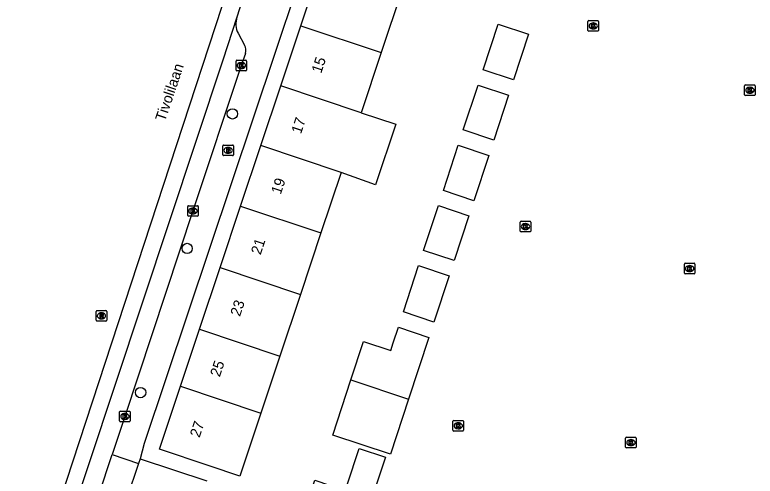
# Model space of a CAD drawing. Extents: x 163150 to 163546, y 380933 to 381635.
# Drawn here: x 163218.8 to 163289.1, y 381514.3 to 381558 of the extents above; entities that cross this region are included whole.
import ezdxf

# ---------------------------------------------------------------- set-up
doc = ezdxf.new("R2010")
doc.units = 0
for name, color, linetype in [('IMGEO_Boom', 7, 'Continuous'), ('IMGEO_Brandkraan', 7, 'Continuous'), ('IMGEO_Fietspad_gesloten', 7, 'Continuous'), ('IMGEO_Kolk', 7, 'Continuous'), ('IMGEO_Openbare_ruimte_label', 7, 'Continuous'), ('IMGEO_Pand', 7, 'Continuous'), ('IMGEO_Pand_nummerreeks', 7, 'Continuous'), ('IMGEO_Rijbaan_lokaal_gesloten', 7, 'Continuous'), ('IMGEO_Rioolput', 7, 'Continuous'), ('IMGEO_Voetpad_open', 7, 'Continuous')]:
    doc.layers.add(name, color=color, linetype=linetype)

msp = doc.modelspace()

# ---------------------------------------------------------------- linework, layer by layer
at = {"layer": 'IMGEO_Boom'}
for centre in [(163239.462, 381548.623), (163235.165, 381535.854), (163230.745, 381522.183)]:
    msp.add_circle(centre, 0.489, dxfattribs=at)
at = {"layer": 'IMGEO_Brandkraan'}
for p, q in [((163238.556, 381544.736), (163238.556, 381545.588)), ((163238.631, 381545.662), (163239.483, 381545.662)), ((163239.044, 381545.442), (163239.069, 381545.442)), ((163239.557, 381545.588), (163239.557, 381544.736)), ((163239.483, 381544.662), (163238.631, 381544.662)), ((163239.067, 381544.882), (163239.042, 381544.882))]:
    msp.add_line(p, q, dxfattribs=at)
for points in [[(163238.556, 381544.736), (163238.556, 381545.588)], [(163238.631, 381545.662), (163239.483, 381545.662)], [(163238.904, 381545.362), (163238.904, 381544.962), (163239.117, 381544.962)], [(163239.135, 381545.362), (163238.904, 381545.362)], [(163239.083, 381545.281), (163239.029, 381545.281), (163239.029, 381545.205)], [(163239.029, 381545.205), (163239.082, 381545.205)], [(163239.091, 381545.129), (163239.029, 381545.129), (163239.029, 381545.048)], [(163239.557, 381545.588), (163239.557, 381544.736)], [(163239.483, 381544.662), (163238.631, 381544.662)], [(163239.029, 381545.048), (163239.091, 381545.048)]]:
    msp.add_lwpolyline(points, dxfattribs=at)
for centre, radius, start, end in [((163238.633, 381545.586), 0.0765, 91.55205, 178.44795), ((163238.633, 381545.586), 0.0765, 91.55205, 178.44795), ((163239.084, 381545.243), 0.0379, 267.82845, 90.93552), ((163239.092, 381545.088), 0.0404, 269.87594, 90.50774), ((163239.139, 381545.217), 0.145, 59.4692, 91.53667), ((163239.164, 381545.264), 0.0922, 285.51372, 58.15012), ((163239.169, 381545.072), 0.105, 301.31148, 78.98903), ((163239.481, 381545.586), 0.0765, 1.55205, 88.44795), ((163239.481, 381545.586), 0.0765, 1.55205, 88.44795), ((163238.633, 381544.738), 0.0765, 181.55205, 268.44795), ((163238.633, 381544.738), 0.0765, 181.55205, 268.44795), ((163239.123, 381545.213), 0.251, 268.66757, 293.53466), ((163239.481, 381544.738), 0.0765, 271.55205, 358.44795), ((163239.481, 381544.738), 0.0765, 271.55205, 358.44795)]:
    msp.add_arc(centre, radius, start, end, dxfattribs=at)
for centre, major_axis, ratio, start_param, end_param in [((163239.043, 381545.162), (-0.387, 0.002), 0.722429, 4.712389, 7.853982), ((163239.068, 381545.162), (-0.39, 0.002), 0.717154, 1.570796, 4.712389)]:
    msp.add_ellipse(centre, major_axis=major_axis, ratio=ratio, start_param=start_param, end_param=end_param, dxfattribs=at)
at = {"layer": 'IMGEO_Fietspad_gesloten'}
for points in [[(163241.214, 381561.974), (163239.892, 381557.795)], [(163239.892, 381557.795), (163238.567, 381553.72), (163220.71, 381500), (163220.06, 381498.046)]]:
    msp.add_lwpolyline(points, dxfattribs=at)
at = {"layer": 'IMGEO_Kolk'}
for p, q in [((163273.225, 381556.542), (163273.225, 381557.394)), ((163273.3, 381557.468), (163274.152, 381557.468)), ((163273.713, 381557.248), (163273.738, 381557.248)), ((163274.226, 381557.394), (163274.226, 381556.542)), ((163274.152, 381556.468), (163273.3, 381556.468)), ((163273.736, 381556.688), (163273.711, 381556.688)), ((163239.809, 381552.783), (163239.809, 381553.635)), ((163239.884, 381553.709), (163240.736, 381553.709)), ((163240.81, 381553.635), (163240.81, 381552.783)), ((163240.32, 381552.929), (163240.295, 381552.929)), ((163240.297, 381553.489), (163240.322, 381553.489)), ((163240.736, 381552.709), (163239.884, 381552.709)), ((163288.104, 381550.444), (163288.104, 381551.296)), ((163288.179, 381551.37), (163289.031, 381551.37)), ((163288.592, 381551.15), (163288.617, 381551.15)), ((163289.105, 381551.296), (163289.105, 381550.444)), ((163289.031, 381550.37), (163288.179, 381550.37)), ((163288.615, 381550.59), (163288.59, 381550.59)), ((163235.216, 381538.988), (163235.216, 381539.84)), ((163235.291, 381539.914), (163236.143, 381539.914)), ((163235.704, 381539.694), (163235.729, 381539.694)), ((163236.217, 381539.84), (163236.217, 381538.988)), ((163236.143, 381538.914), (163235.291, 381538.914)), ((163235.727, 381539.134), (163235.702, 381539.134)), ((163266.797, 381537.508), (163266.797, 381538.36)), ((163266.872, 381538.434), (163267.724, 381538.434)), ((163267.285, 381538.214), (163267.31, 381538.214)), ((163267.798, 381538.36), (163267.798, 381537.508)), ((163267.724, 381537.434), (163266.872, 381537.434)), ((163267.308, 381537.654), (163267.283, 381537.654)), ((163282.381, 381533.522), (163282.381, 381534.374)), ((163282.456, 381534.448), (163283.308, 381534.448)), ((163282.869, 381534.228), (163282.894, 381534.228)), ((163283.382, 381534.374), (163283.382, 381533.522)), ((163283.308, 381533.448), (163282.456, 381533.448)), ((163282.892, 381533.668), (163282.867, 381533.668)), ((163228.756, 381519.491), (163228.756, 381520.343)), ((163228.831, 381520.417), (163229.683, 381520.417)), ((163229.244, 381520.197), (163229.269, 381520.197)), ((163229.757, 381520.343), (163229.757, 381519.491)), ((163229.683, 381519.417), (163228.831, 381519.417)), ((163229.267, 381519.637), (163229.242, 381519.637)), ((163260.408, 381518.604), (163260.408, 381519.456)), ((163260.483, 381519.53), (163261.335, 381519.53)), ((163260.896, 381519.31), (163260.921, 381519.31)), ((163261.409, 381519.456), (163261.409, 381518.604)), ((163261.335, 381518.53), (163260.483, 381518.53)), ((163260.919, 381518.75), (163260.894, 381518.75)), ((163276.804, 381517.015), (163276.804, 381517.867)), ((163276.879, 381517.941), (163277.731, 381517.941)), ((163277.292, 381517.721), (163277.317, 381517.721)), ((163277.805, 381517.867), (163277.805, 381517.015)), ((163277.315, 381517.161), (163277.29, 381517.161)), ((163277.731, 381516.941), (163276.879, 381516.941))]:
    msp.add_line(p, q, dxfattribs=at)
for points in [[(163273.225, 381556.542), (163273.225, 381557.394)], [(163273.3, 381557.468), (163274.152, 381557.468)], [(163273.546, 381557.168), (163273.669, 381557.168), (163273.669, 381557.017), (163273.799, 381557.168), (163273.963, 381557.168), (163273.817, 381557.017), (163273.97, 381556.768), (163273.818, 381556.768), (163273.733, 381556.932), (163273.669, 381556.865), (163273.669, 381556.768), (163273.546, 381556.768), (163273.546, 381557.168)], [(163274.226, 381557.394), (163274.226, 381556.542)], [(163274.152, 381556.468), (163273.3, 381556.468)], [(163239.809, 381552.783), (163239.809, 381553.635)], [(163239.884, 381553.709), (163240.736, 381553.709)], [(163240.81, 381553.635), (163240.81, 381552.783)], [(163240.13, 381553.409), (163240.253, 381553.409), (163240.253, 381553.258), (163240.383, 381553.409), (163240.547, 381553.409), (163240.401, 381553.258), (163240.554, 381553.009), (163240.402, 381553.009), (163240.317, 381553.173), (163240.253, 381553.106), (163240.253, 381553.009), (163240.13, 381553.009), (163240.13, 381553.409)], [(163240.736, 381552.709), (163239.884, 381552.709)], [(163288.104, 381550.444), (163288.104, 381551.296)], [(163288.179, 381551.37), (163289.031, 381551.37)], [(163288.425, 381551.07), (163288.548, 381551.07), (163288.548, 381550.919), (163288.678, 381551.07), (163288.842, 381551.07), (163288.696, 381550.919), (163288.849, 381550.67), (163288.697, 381550.67), (163288.612, 381550.834), (163288.548, 381550.767), (163288.548, 381550.67), (163288.425, 381550.67), (163288.425, 381551.07)], [(163289.105, 381551.296), (163289.105, 381550.444)], [(163289.031, 381550.37), (163288.179, 381550.37)], [(163235.216, 381538.988), (163235.216, 381539.84)], [(163235.291, 381539.914), (163236.143, 381539.914)], [(163235.537, 381539.614), (163235.66, 381539.614), (163235.66, 381539.463), (163235.79, 381539.614), (163235.954, 381539.614), (163235.808, 381539.463), (163235.961, 381539.214), (163235.809, 381539.214), (163235.724, 381539.378), (163235.66, 381539.311), (163235.66, 381539.214), (163235.537, 381539.214), (163235.537, 381539.614)], [(163236.217, 381539.84), (163236.217, 381538.988)], [(163236.143, 381538.914), (163235.291, 381538.914)], [(163266.797, 381537.508), (163266.797, 381538.36)], [(163266.872, 381538.434), (163267.724, 381538.434)], [(163267.118, 381538.134), (163267.241, 381538.134), (163267.241, 381537.983), (163267.371, 381538.134), (163267.535, 381538.134), (163267.389, 381537.983), (163267.542, 381537.734), (163267.39, 381537.734), (163267.305, 381537.898), (163267.241, 381537.831), (163267.241, 381537.734), (163267.118, 381537.734), (163267.118, 381538.134)], [(163267.798, 381538.36), (163267.798, 381537.508)], [(163267.724, 381537.434), (163266.872, 381537.434)], [(163282.381, 381533.522), (163282.381, 381534.374)], [(163282.456, 381534.448), (163283.308, 381534.448)], [(163282.702, 381534.148), (163282.825, 381534.148), (163282.825, 381533.997), (163282.955, 381534.148), (163283.119, 381534.148), (163282.973, 381533.997), (163283.126, 381533.748), (163282.974, 381533.748), (163282.889, 381533.912), (163282.825, 381533.845), (163282.825, 381533.748), (163282.702, 381533.748), (163282.702, 381534.148)], [(163283.382, 381534.374), (163283.382, 381533.522)], [(163283.308, 381533.448), (163282.456, 381533.448)], [(163228.756, 381519.491), (163228.756, 381520.343)], [(163228.831, 381520.417), (163229.683, 381520.417)], [(163229.077, 381520.117), (163229.2, 381520.117), (163229.2, 381519.966), (163229.33, 381520.117), (163229.494, 381520.117), (163229.348, 381519.966), (163229.501, 381519.717), (163229.349, 381519.717), (163229.264, 381519.881), (163229.2, 381519.814), (163229.2, 381519.717), (163229.077, 381519.717), (163229.077, 381520.117)], [(163229.757, 381520.343), (163229.757, 381519.491)], [(163229.683, 381519.417), (163228.831, 381519.417)], [(163260.408, 381518.604), (163260.408, 381519.456)], [(163260.483, 381519.53), (163261.335, 381519.53)], [(163260.729, 381519.23), (163260.852, 381519.23), (163260.852, 381519.079), (163260.982, 381519.23), (163261.146, 381519.23), (163261, 381519.079), (163261.153, 381518.83), (163261.001, 381518.83), (163260.916, 381518.994), (163260.852, 381518.927), (163260.852, 381518.83), (163260.729, 381518.83), (163260.729, 381519.23)], [(163261.409, 381519.456), (163261.409, 381518.604)], [(163261.335, 381518.53), (163260.483, 381518.53)], [(163276.804, 381517.015), (163276.804, 381517.867)], [(163276.879, 381517.941), (163277.731, 381517.941)], [(163277.805, 381517.867), (163277.805, 381517.015)], [(163277.125, 381517.641), (163277.248, 381517.641), (163277.248, 381517.49), (163277.378, 381517.641), (163277.542, 381517.641), (163277.396, 381517.49), (163277.549, 381517.241), (163277.397, 381517.241), (163277.312, 381517.405), (163277.248, 381517.338), (163277.248, 381517.241), (163277.125, 381517.241), (163277.125, 381517.641)], [(163277.731, 381516.941), (163276.879, 381516.941)]]:
    msp.add_lwpolyline(points, dxfattribs=at)
for centre, start, end in [((163273.302, 381557.392), 91.55205, 178.44795), ((163273.302, 381557.392), 91.55205, 178.44795), ((163274.15, 381557.392), 1.55205, 88.44795), ((163274.15, 381557.392), 1.55205, 88.44795), ((163273.302, 381556.544), 181.55205, 268.44795), ((163273.302, 381556.544), 181.55205, 268.44795), ((163274.15, 381556.544), 271.55205, 358.44795), ((163274.15, 381556.544), 271.55205, 358.44795), ((163239.886, 381553.633), 91.55205, 178.44795), ((163239.886, 381553.633), 91.55205, 178.44795), ((163240.734, 381553.633), 1.55205, 88.44795), ((163240.734, 381553.633), 1.55205, 88.44795), ((163239.886, 381552.785), 181.55205, 268.44795), ((163239.886, 381552.785), 181.55205, 268.44795), ((163240.734, 381552.785), 271.55205, 358.44795), ((163240.734, 381552.785), 271.55205, 358.44795), ((163288.181, 381551.294), 91.55205, 178.44795), ((163288.181, 381551.294), 91.55205, 178.44795), ((163289.029, 381551.294), 1.55205, 88.44795), ((163289.029, 381551.294), 1.55205, 88.44795), ((163288.181, 381550.446), 181.55205, 268.44795), ((163288.181, 381550.446), 181.55205, 268.44795), ((163289.029, 381550.446), 271.55205, 358.44795), ((163289.029, 381550.446), 271.55205, 358.44795), ((163235.293, 381539.838), 91.55205, 178.44795), ((163235.293, 381539.838), 91.55205, 178.44795), ((163236.141, 381539.838), 1.55205, 88.44795), ((163236.141, 381539.838), 1.55205, 88.44795), ((163235.293, 381538.99), 181.55205, 268.44795), ((163235.293, 381538.99), 181.55205, 268.44795), ((163236.141, 381538.99), 271.55205, 358.44795), ((163236.141, 381538.99), 271.55205, 358.44795), ((163266.874, 381538.358), 91.55205, 178.44795), ((163266.874, 381538.358), 91.55205, 178.44795), ((163267.722, 381538.358), 1.55205, 88.44795), ((163267.722, 381538.358), 1.55205, 88.44795), ((163266.874, 381537.51), 181.55205, 268.44795), ((163266.874, 381537.51), 181.55205, 268.44795), ((163267.722, 381537.51), 271.55205, 358.44795), ((163267.722, 381537.51), 271.55205, 358.44795), ((163282.458, 381534.372), 91.55205, 178.44795), ((163282.458, 381534.372), 91.55205, 178.44795), ((163283.306, 381534.372), 1.55205, 88.44795), ((163283.306, 381534.372), 1.55205, 88.44795), ((163282.458, 381533.524), 181.55205, 268.44795), ((163282.458, 381533.524), 181.55205, 268.44795), ((163283.306, 381533.524), 271.55205, 358.44795), ((163283.306, 381533.524), 271.55205, 358.44795), ((163228.833, 381520.341), 91.55205, 178.44795), ((163228.833, 381520.341), 91.55205, 178.44795), ((163229.681, 381520.341), 1.55205, 88.44795), ((163229.681, 381520.341), 1.55205, 88.44795), ((163228.833, 381519.493), 181.55205, 268.44795), ((163228.833, 381519.493), 181.55205, 268.44795), ((163229.681, 381519.493), 271.55205, 358.44795), ((163229.681, 381519.493), 271.55205, 358.44795), ((163260.485, 381519.454), 91.55205, 178.44795), ((163260.485, 381519.454), 91.55205, 178.44795), ((163261.333, 381519.454), 1.55205, 88.44795), ((163261.333, 381519.454), 1.55205, 88.44795), ((163260.485, 381518.606), 181.55205, 268.44795), ((163260.485, 381518.606), 181.55205, 268.44795), ((163261.333, 381518.606), 271.55205, 358.44795), ((163261.333, 381518.606), 271.55205, 358.44795), ((163276.881, 381517.865), 91.55205, 178.44795), ((163276.881, 381517.865), 91.55205, 178.44795), ((163277.729, 381517.865), 1.55205, 88.44795), ((163277.729, 381517.865), 1.55205, 88.44795), ((163276.881, 381517.017), 181.55205, 268.44795), ((163276.881, 381517.017), 181.55205, 268.44795), ((163277.729, 381517.017), 271.55205, 358.44795), ((163277.729, 381517.017), 271.55205, 358.44795)]:
    msp.add_arc(centre, 0.0765, start, end, dxfattribs=at)
for centre, major_axis, ratio, start_param, end_param in [((163273.712, 381556.968), (-0.387, 0.002), 0.722429, 4.712389, 7.853982), ((163273.737, 381556.968), (-0.39, 0.002), 0.717154, 1.570796, 4.712389), ((163240.296, 381553.209), (-0.387, 0.002), 0.722429, 4.712389, 7.853982), ((163240.321, 381553.209), (-0.39, 0.002), 0.717154, 1.570796, 4.712389), ((163288.591, 381550.87), (-0.387, 0.002), 0.722429, 4.712389, 7.853982), ((163288.616, 381550.87), (-0.39, 0.002), 0.717154, 1.570796, 4.712389), ((163235.703, 381539.414), (-0.387, 0.002), 0.722429, 4.712389, 7.853982), ((163235.728, 381539.414), (-0.39, 0.002), 0.717154, 1.570796, 4.712389), ((163267.284, 381537.934), (-0.387, 0.002), 0.722429, 4.712389, 7.853982), ((163267.309, 381537.934), (-0.39, 0.002), 0.717154, 1.570796, 4.712389), ((163282.868, 381533.948), (-0.387, 0.002), 0.722429, 4.712389, 7.853982), ((163282.893, 381533.948), (-0.39, 0.002), 0.717154, 1.570796, 4.712389), ((163229.243, 381519.917), (-0.387, 0.002), 0.722429, 4.712389, 7.853982), ((163229.268, 381519.917), (-0.39, 0.002), 0.717154, 1.570796, 4.712389), ((163260.895, 381519.03), (-0.387, 0.002), 0.722429, 4.712389, 7.853982), ((163260.92, 381519.03), (-0.39, 0.002), 0.717154, 1.570796, 4.712389), ((163277.291, 381517.441), (-0.387, 0.002), 0.722429, 4.712389, 7.853982), ((163277.316, 381517.441), (-0.39, 0.002), 0.717154, 1.570796, 4.712389)]:
    msp.add_ellipse(centre, major_axis=major_axis, ratio=ratio, start_param=start_param, end_param=end_param, dxfattribs=at)
at = {"layer": 'IMGEO_Pand'}
for points in [[(163245.966, 381556.982), (163247.938, 381562.876)], [(163255.562, 381560.327), (163253.59, 381554.433)], [(163266.157, 381551.838), (163263.27, 381552.803), (163264.696, 381557.128), (163267.587, 381556.175), (163266.157, 381551.838)], [(163244.059, 381551.281), (163245.966, 381556.982)], [(163245.966, 381556.982), (163253.59, 381554.433)], [(163253.59, 381554.433), (163251.683, 381548.732)], [(163242.166, 381545.624), (163244.059, 381551.281)], [(163251.683, 381548.732), (163244.059, 381551.281)], [(163264.275, 381546.128), (163261.389, 381547.094), (163262.793, 381551.356), (163265.68, 381550.391), (163264.275, 381546.128)], [(163251.683, 381548.732), (163254.974, 381547.634), (163253.057, 381541.902), (163249.784, 381543.054)], [(163240.245, 381539.882), (163242.166, 381545.624)], [(163249.784, 381543.054), (163242.166, 381545.624)], [(163262.383, 381540.388), (163259.499, 381541.361), (163260.912, 381545.647), (163263.798, 381544.681), (163262.383, 381540.388)], [(163249.784, 381543.054), (163247.87, 381537.332)], [(163238.295, 381534.051), (163240.245, 381539.882)], [(163240.245, 381539.882), (163247.87, 381537.332)], [(163260.508, 381534.698), (163257.621, 381535.663), (163259.029, 381539.935), (163261.913, 381538.962), (163260.508, 381534.698)], [(163247.87, 381537.332), (163245.919, 381531.5)], [(163236.338, 381528.2), (163238.295, 381534.051)], [(163238.295, 381534.051), (163245.919, 381531.5)], [(163258.586, 381528.869), (163255.7, 381529.835), (163257.148, 381534.229), (163260.035, 381533.264), (163258.586, 381528.869)], [(163245.919, 381531.5), (163243.962, 381525.649)], [(163234.525, 381522.783), (163236.338, 381528.2)], [(163236.338, 381528.2), (163243.962, 381525.649)], [(163250.722, 381523.387), (163251.923, 381527.031), (163254.496, 381526.183), (163254.73, 381526.893), (163255.223, 381528.387), (163258.109, 381527.421), (163256.178, 381521.562)], [(163243.962, 381525.649), (163242.15, 381520.232)], [(163256.178, 381521.562), (163254.459, 381516.346), (163248.995, 381518.147), (163250.722, 381523.387)], [(163250.722, 381523.387), (163256.178, 381521.562)], [(163242.15, 381520.232), (163240.152, 381514.261), (163237.27, 381515.226), (163232.528, 381516.812), (163234.525, 381522.783)], [(163234.525, 381522.783), (163242.15, 381520.232)], [(163246.236, 381510.75), (163247.285, 381513.875), (163250.175, 381512.905), (163250.348, 381513.422), (163251.51, 381516.885), (163254.007, 381516.046), (163251.602, 381508.881), (163246.236, 381510.75)], [(163230.707, 381515.914), (163230.55, 381515.445)], [(163230.707, 381515.914), (163237.033, 381513.798)], [(163230.55, 381515.445), (163229.448, 381512.152)]]:
    msp.add_lwpolyline(points, dxfattribs=at)
at = {"layer": 'IMGEO_Rijbaan_lokaal_gesloten'}
msp.add_lwpolyline([(163166.425, 381280.691), (163188.546, 381358.485), (163194.244, 381378.759), (163197.853, 381391.449), (163199.503, 381397.64), (163199.813, 381399.806), (163200.997, 381406.978), (163202.361, 381414.066), (163203.421, 381419.565), (163203.421, 381421.474), (163203.421, 381430.45), (163203.421, 381436.022), (163203.704, 381437.827), (163206.489, 381449.486), (163214.12, 381481.676), (163216.801, 381492.716), (163218.451, 381497.565), (163223.711, 381513.764), (163241.568, 381568.239), (163248.986, 381592.289), (163253.519, 381605.619), (163255.545, 381608.986), (163259.826, 381616.311)], dxfattribs=at)
at = {"layer": 'IMGEO_Rioolput'}
for p, q in [((163226.523, 381529.038), (163226.523, 381529.89)), ((163226.598, 381529.964), (163227.45, 381529.964)), ((163227.011, 381529.744), (163227.036, 381529.744)), ((163227.524, 381529.89), (163227.524, 381529.038)), ((163227.45, 381528.964), (163226.598, 381528.964)), ((163227.034, 381529.184), (163227.009, 381529.184))]:
    msp.add_line(p, q, dxfattribs=at)
for points in [[(163226.523, 381529.038), (163226.523, 381529.89)], [(163226.598, 381529.964), (163227.45, 381529.964)], [(163227.112, 381529.662), (163226.86, 381529.664), (163226.86, 381529.264)], [(163227.524, 381529.89), (163227.524, 381529.038)], [(163227.45, 381528.964), (163226.598, 381528.964)], [(163226.86, 381529.264), (163226.984, 381529.264), (163226.984, 381529.426), (163226.995, 381529.426)], [(163227.038, 381529.583), (163226.984, 381529.583), (163226.984, 381529.502)], [(163226.984, 381529.502), (163227.036, 381529.502)], [(163227.042, 381529.397), (163227.113, 381529.264), (163227.253, 381529.264), (163227.188, 381529.39)]]:
    msp.add_lwpolyline(points, dxfattribs=at)
for centre, radius, start, end in [((163226.6, 381529.888), 0.0765, 91.55205, 178.44795), ((163226.6, 381529.888), 0.0765, 91.55205, 178.44795), ((163227.111, 381529.552), 0.109, 350.36119, 89.41601), ((163227.448, 381529.888), 0.0765, 1.55205, 88.44795), ((163227.448, 381529.888), 0.0765, 1.55205, 88.44795), ((163226.6, 381529.04), 0.0765, 181.55205, 268.44795), ((163226.6, 381529.04), 0.0765, 181.55205, 268.44795), ((163226.994, 381529.373), 0.0533, 26.02933, 88.69889), ((163227.02, 381529.691), 0.19, 274.7715, 282.96867), ((163227.044, 381529.487), 0.0964, 77.00612, 93.18647), ((163227.058, 381529.544), 0.0378, 276.66336, 79.67722), ((163227.109, 381529.552), 0.112, 277.58423, 350.98172), ((163227.093, 381529.337), 0.108, 29.51342, 73.79051), ((163227.448, 381529.04), 0.0765, 271.55205, 358.44795), ((163227.448, 381529.04), 0.0765, 271.55205, 358.44795)]:
    msp.add_arc(centre, radius, start, end, dxfattribs=at)
for centre, major_axis, ratio, start_param, end_param in [((163227.01, 381529.464), (-0.387, 0.002), 0.722429, 4.712389, 7.853982), ((163227.035, 381529.464), (-0.39, 0.002), 0.717154, 1.570796, 4.712389)]:
    msp.add_ellipse(centre, major_axis=major_axis, ratio=ratio, start_param=start_param, end_param=end_param, dxfattribs=at)
at = {"layer": 'IMGEO_Voetpad_open'}
for points in [[(163259.425, 381597.215), (163258.011, 381597.702), (163231.091, 381517.353), (163230.707, 381515.914)], [(163240, 381556.264), (163240.606, 381555.126)], [(163240.693, 381554.364), (163240.304, 381553.21), (163235.712, 381539.414), (163229.252, 381519.917), (163228.034, 381516.302)], [(163225.534, 381508.756), (163228.034, 381516.302)], [(163228.034, 381516.302), (163230.55, 381515.445)]]:
    msp.add_lwpolyline(points, dxfattribs=at)
for centre, radius, start, end in [((163241.866, 381557.165), 2.072, 162.29325, 205.77692), ((163239.833, 381554.652), 0.907, 341.49219, 31.53469)]:
    msp.add_arc(centre, radius, start, end, dxfattribs=at)

# ---------------------------------------------------------------- texts
at = {"layer": 'IMGEO_Openbare_ruimte_label'}
msp.add_text('Tivolilaan', height=1, rotation=71.32942, dxfattribs=at).set_placement((163233.055, 381547.843))
at = {"layer": 'IMGEO_Pand_nummerreeks'}
for s, p in [('15', (163247.893, 381552.404)), ('17', (163245.972, 381546.661)), ('19', (163244.051, 381540.918)), ('21', (163242.136, 381535.196)), ('23', (163240.18, 381529.346)), ('25', (163238.259, 381523.603)), ('27', (163236.338, 381517.86))]:
    msp.add_text(s, height=1, rotation=71.5035, dxfattribs=at).set_placement(p)

doc.saveas('drawing.dxf')
